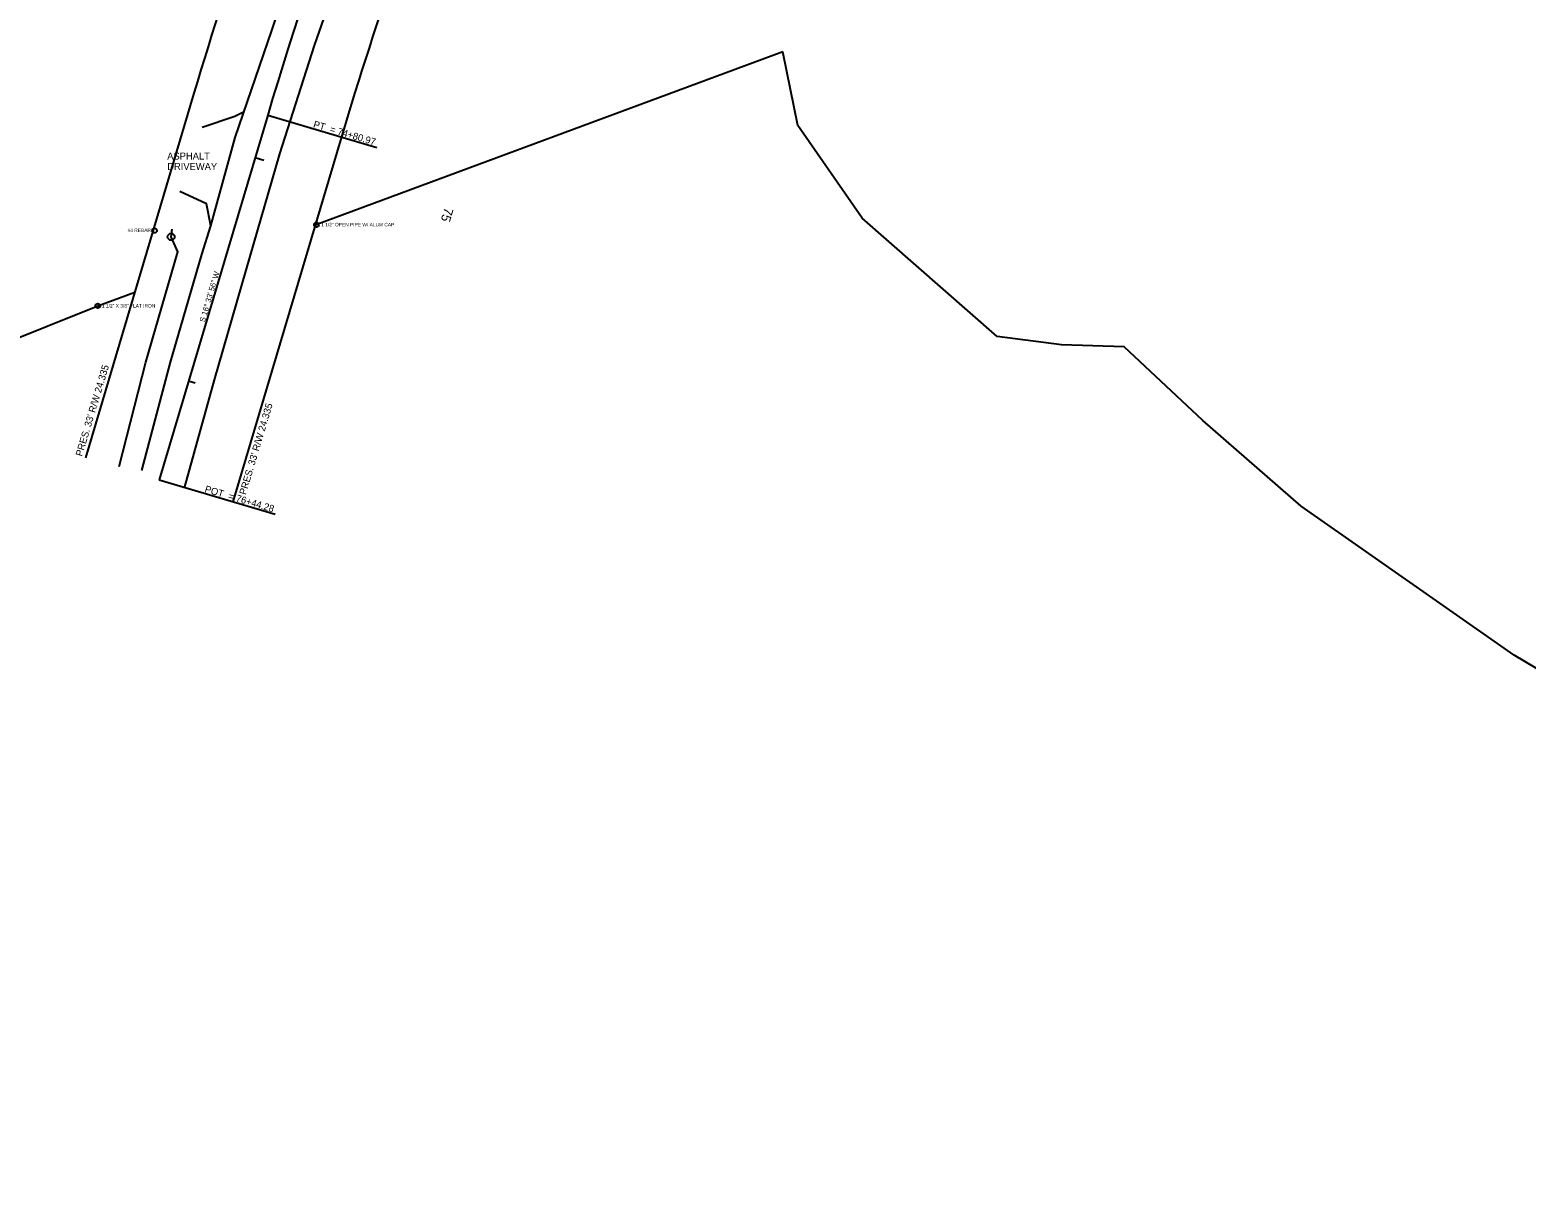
# Model space of a CAD drawing. Extents: x 1628604 to 1635417, y 886385 to 890338.
# Drawn here: x 1631014 to 1631655, y 887573 to 888076 of the extents above; entities that cross this region are included whole.
import ezdxf

# ---------------------------------------------------------------- set-up
doc = ezdxf.new("R2010")
doc.units = 0
for name, color, linetype in [('RD_EX_DV_Prop', 7, 'Continuous'), ('RD_EX_DV_Prop_txCode', 7, 'Continuous'), ('RD_EX_DV_PropPin', 7, 'Continuous'), ('RD_EX_Road', 7, 'Continuous'), ('RD_EX_RW', 7, 'Continuous'), ('RD_EX_RW_TX', 7, 'Continuous'), ('RD_EX_SU_Telecom', 7, 'Continuous'), ('RD_EX_UT', 7, 'Continuous'), ('RD_HC_Cl', 7, 'Continuous'), ('RD_HC_Data', 7, 'Continuous'), ('RD_HC_Data_Tic', 7, 'Continuous'), ('RD_HC_TX_Sta20', 7, 'Continuous'), ('RD_TX_Misc1', 7, 'Continuous')]:
    doc.layers.add(name, color=color, linetype=linetype)

msp = doc.modelspace()

# ---------------------------------------------------------------- linework, layer by layer
at = {"layer": 'RD_EX_DV_Prop'}
for points in [[(1631336.59, 888066.6), (1631135.94, 887992.16)], [(1632199.1, 887573.35), (1631820.12, 887748.1), (1631779.19, 887762.77), (1631744.15, 887766.47), (1631685.09, 887786.83), (1631650.29, 887807.62), (1631558.85, 887871.61), (1631516.65, 887908.33), (1631482.95, 887939.96), (1631456.1, 887940.84), (1631428.42, 887944.35), (1631370.51, 887995.16), (1631342.93, 888034.88), (1631336.59, 888066.6)], [(1630109.43, 887582.92), (1631042.66, 887957.55), (1631058.54, 887963.44)]]:
    msp.add_lwpolyline(points, dxfattribs=at)
at = {"layer": 'RD_EX_DV_PropPin'}
for centre in [(1631136.48, 887992.36), (1631067.06, 887989.82), (1631042.66, 887957.55)]:
    msp.add_circle(centre, 1, dxfattribs=at)
at = {"layer": 'RD_EX_Road'}
for points in [[(1631061.65, 887886.91), (1631073.86, 887933.34), (1631087.39, 887979.64), (1631091.12, 887991.9), (1631101.62, 888029.8), (1631117.32, 888075.69), (1631134.95, 888128.02), (1631152.2, 888175.32), (1631171.74, 888224.62), (1631193.53, 888274.89), (1631216.42, 888321.99), (1631241.71, 888367.79), (1631266.25, 888411.67), (1631264.25, 888413), (1631299.43, 888478.7), (1631304.13, 888476.05), (1631327.2, 888511.47)], [(1631080.06, 887879.92), (1631092.71, 887925.82), (1631106.29, 887972.84), (1631120.8, 888022.75), (1631135.69, 888069.29), (1631152.84, 888118.51), (1631170.28, 888166.75), (1631190.48, 888217.25), (1631211.83, 888266.99), (1631234.52, 888311.47), (1631258.75, 888356.69), (1631283.38, 888401.46), (1631286.15, 888399.98), (1631324.47, 888464.12), (1631322.12, 888465.29), (1631348.79, 888509.12)], [(1631087.52, 888034.19), (1631101.45, 888038.87), (1631105.43, 888040.97)], [(1631091.12, 887991.9), (1631089.3, 888001.29), (1631077.88, 888006.66)]]:
    msp.add_lwpolyline(points, dxfattribs=at)
at = {"layer": 'RD_EX_RW'}
for p, q in [((1631083.94, 888048.83), (1631037.38, 887892.3)), ((1631147.21, 888030.01), (1631100.64, 887873.48))]:
    msp.add_line(p, q, dxfattribs=at)
for radius in [1737.45, 1671.45]:
    msp.add_arc((1632749.28, 887553.47), radius, 152.47845, 163.43457, dxfattribs=at)
at = {"layer": 'RD_EX_SU_Telecom'}
msp.add_lwpolyline([(1631051.84, 887888.61), (1631063.28, 887933.3), (1631077.06, 887980.78), (1631074.16, 887987.16), (1631074.64, 887990.5)], dxfattribs=at)
at = {"layer": 'RD_EX_UT'}
msp.add_circle((1631074.16, 887987.16), 1.5, dxfattribs=at)
at = {"layer": 'RD_HC_Cl'}
msp.add_line((1631115.57, 888039.42), (1631069.01, 887882.89), dxfattribs=at)
msp.add_arc((1632749.28, 887553.47), 1704.45, 147.5244, 163.43457, dxfattribs=at)
at = {"layer": 'RD_HC_Data'}
for p, q in [((1631115.57, 888039.42), (1631162.33, 888025.51)), ((1631069.01, 887882.89), (1631118.71, 887868.11))]:
    msp.add_line(p, q, dxfattribs=at)
at = {"layer": 'RD_HC_Data_Tic'}
for p, q in [((1631110.15, 888021.19), (1631113.98, 888020.05)), ((1631081.64, 887925.34), (1631084.51, 887924.48))]:
    msp.add_line(p, q, dxfattribs=at)

# ---------------------------------------------------------------- texts
at = {"layer": 'RD_EX_DV_Prop_txCode'}
for s, p in [('1 1/2" OPEN PIPE W/ ALUM CAP', (1631138.53, 887991.66)), ('#4 REBAR', (1631055.45, 887989.23)), ('1 1/2" X 3/8" FLAT IRON', (1631044.47, 887956.81))]:
    msp.add_text(s, height=1.5, dxfattribs=at).set_placement(p)
at = {"layer": 'RD_EX_RW_TX'}
for p in [(1631035.95, 887892.73), (1631106.16, 887876.24)]:
    msp.add_text("PRES. 33' R/W 24.335", height=3, rotation=73.43457, dxfattribs=at).set_placement(p)
at = {"layer": 'RD_EX_UT'}
msp.add_text('T', height=1.5, rotation=360, dxfattribs=at).set_placement((1631073.81, 887986.34))
at = {"layer": 'RD_HC_Data'}
for s, height, rotation, p in [('PT  = 74+80.97', 3, 343.43457, (1631134.89, 888034.2)), ('S 16%%d 33\' 56" W', 2.4, 73.43457, (1631088.55, 887950.34)), ('POT  = 76+44.28', 3, 343.43457, (1631088.33, 887877.67))]:
    msp.add_text(s, height=height, rotation=rotation, dxfattribs=at).set_placement(p)
at = {"layer": 'RD_HC_TX_Sta20'}
msp.add_text('75', height=4, rotation=253.43457, dxfattribs=at).set_placement((1631191.48, 888000))
at = {"layer": 'RD_TX_Misc1'}
for s, p in [('ASPHALT', (1631072.49, 888020.34)), ('DRIVEWAY', (1631072.49, 888015.84))]:
    msp.add_text(s, height=3, dxfattribs=at).set_placement(p)

doc.saveas('drawing.dxf')
